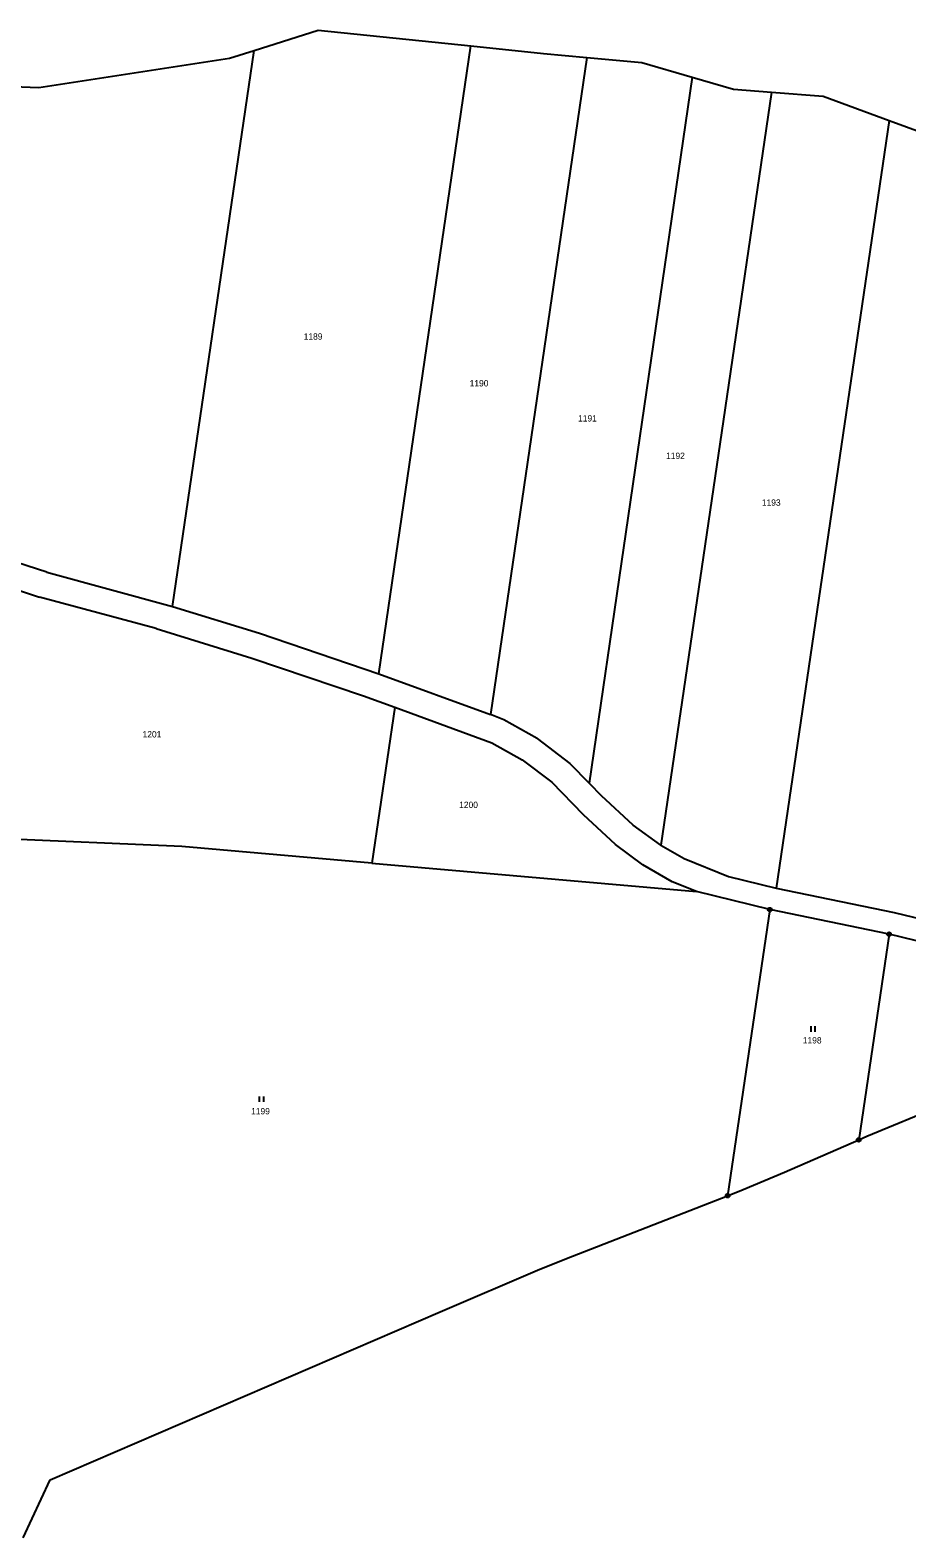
# Model space of a CAD drawing. Extents: x -796130 to -793145, y -1109506 to -1106267.
# Drawn here: x -794165.1 to -793929.1, y -1109343.1 to -1108937.3 of the extents above; entities that cross this region are included whole.
import ezdxf

# ---------------------------------------------------------------- set-up
doc = ezdxf.new("R2010")
doc.units = 0
for name, color, linetype in [('Vrstva 1', 7, 'Continuous'), ('Vrstva 14', 7, 'Continuous'), ('Vrstva 23', 7, 'Continuous'), ('Vrstva 28', 7, 'Continuous'), ('Vrstva 4', 7, 'Continuous')]:
    doc.layers.add(name, color=color, linetype=linetype)

msp = doc.modelspace()

# ---------------------------------------------------------------- linework, layer by layer
at = {"layer": 'Vrstva 1'}
for p, q in [((-794104.82, -1108942.73), (-794087.59, -1108937.28)), ((-794087.59, -1108937.28), (-794046.51, -1108941.52)), ((-794071.22, -1109110.53), (-794046.51, -1108941.52)), ((-794046.51, -1108941.52), (-794026.92, -1108943.54)), ((-794162.78, -1108952.68), (-794111.4, -1108944.81)), ((-794126.72, -1109092.42), (-794104.82, -1108942.73)), ((-794111.4, -1108944.81), (-794104.82, -1108942.73)), ((-794015.27, -1108944.62), (-794041.14, -1109121.51)), ((-794026.92, -1108943.54), (-794015.27, -1108944.62)), ((-794015.27, -1108944.62), (-794000.44, -1108945.99)), ((-794000.44, -1108945.99), (-793986.88, -1108949.93)), ((-793986.88, -1108949.93), (-794014.67, -1109139.95)), ((-793986.88, -1108949.93), (-793975.78, -1108953.15)), ((-794183.38, -1108951.9), (-794162.78, -1108952.68)), ((-793965.54, -1108953.96), (-793979.48, -1109048.73)), ((-793975.78, -1108953.15), (-793965.54, -1108953.96)), ((-793965.54, -1108953.96), (-793951.63, -1108955.05)), ((-793951.63, -1108955.05), (-793933.87, -1108961.6)), ((-793933.87, -1108961.6), (-793948.03, -1109057.9)), ((-793933.87, -1108961.6), (-793916, -1108968.2)), ((-793979.48, -1109048.73), (-793995.35, -1109156.64)), ((-793948.03, -1109057.9), (-793964.26, -1109168.26)), ((-794160.54, -1109083.19), (-794195.6, -1109071.85)), ((-794185.21, -1109082.53), (-794162.53, -1109089.9)), ((-794160.54, -1109083.19), (-794126.72, -1109092.42)), ((-794131.17, -1109098.37), (-794162.53, -1109089.9)), ((-794126.72, -1109092.42), (-794103.37, -1109099.6)), ((-794131.17, -1109098.37), (-794105.39, -1109106.3)), ((-794103.37, -1109099.6), (-794071.22, -1109110.53)), ((-794105.39, -1109106.3), (-794075.38, -1109116.47)), ((-794071.22, -1109110.53), (-794041.14, -1109121.51)), ((-794075.38, -1109116.47), (-794066.93, -1109119.55)), ((-794066.93, -1109119.55), (-794073.1, -1109161.53)), ((-794066.93, -1109119.55), (-794040.84, -1109129.07)), ((-794037.56, -1109122.88), (-794041.14, -1109121.51)), ((-794028.59, -1109127.95), (-794037.56, -1109122.88)), ((-794040.84, -1109129.07), (-794032.64, -1109133.65)), ((-794028.59, -1109127.95), (-794019.8, -1109134.66)), ((-794032.64, -1109133.65), (-794024.67, -1109139.69)), ((-794019.8, -1109134.66), (-794014.67, -1109139.95)), ((-794016.14, -1109148.5), (-794024.67, -1109139.69)), ((-794014.67, -1109139.95), (-794011.32, -1109143.41)), ((-794002.78, -1109151.3), (-794011.32, -1109143.41)), ((-794007.55, -1109156.46), (-794016.14, -1109148.5)), ((-793995.35, -1109156.64), (-794002.78, -1109151.3)), ((-794124.24, -1109157.05), (-794195.74, -1109153.92)), ((-794073.1, -1109161.53), (-794124.24, -1109157.05)), ((-794000.16, -1109161.93), (-794007.55, -1109156.46)), ((-793995.35, -1109156.64), (-793989.07, -1109160.29)), ((-794073.1, -1109161.53), (-793985.71, -1109169.17)), ((-793989.07, -1109160.29), (-793977.09, -1109165.05)), ((-793992.26, -1109166.53), (-794000.16, -1109161.93)), ((-793977.09, -1109165.05), (-793964.26, -1109168.26)), ((-793985.71, -1109169.17), (-793992.26, -1109166.53)), ((-793966.01, -1109174.01), (-793985.71, -1109169.17)), ((-793964.26, -1109168.26), (-793932.54, -1109174.79)), ((-793966.01, -1109174.01), (-793977.36, -1109251.01)), ((-793933.93, -1109180.62), (-793966.01, -1109174.01)), ((-793932.54, -1109174.79), (-793916.12, -1109178.76)), ((-793933.93, -1109180.62), (-793942.09, -1109235.98)), ((-793917.53, -1109184.59), (-793933.93, -1109180.62))]:
    msp.add_line(p, q, dxfattribs=at)
at = {"layer": 'Vrstva 23'}
for p, q in [((-793954.91, -1109206.92), (-793954.91, -1109205.42)), ((-793953.91, -1109205.42), (-793953.91, -1109206.92)), ((-794103.31, -1109225.78), (-794103.31, -1109224.28)), ((-794102.31, -1109224.28), (-794102.31, -1109225.78))]:
    msp.add_line(p, q, dxfattribs=at)
at = {"layer": 'Vrstva 28'}
for centre, radius in [((-793966.01, -1109174.01), 0.5), ((-793966.01, -1109174.01), 0.01), ((-793933.93, -1109180.62), 0.5), ((-793933.93, -1109180.62), 0.01), ((-793942.09, -1109235.98), 0.5), ((-793942.09, -1109235.98), 0.01), ((-793977.36, -1109251.01), 0.5), ((-793977.36, -1109251.01), 0.01)]:
    msp.add_circle(centre, radius, dxfattribs=at)
at = {"layer": 'Vrstva 4'}
for p, q in [((-793939.91, -1109235.03), (-793850.35, -1109197.8)), ((-793962.05, -1109244.72), (-793942.09, -1109235.98)), ((-793942.09, -1109235.98), (-793939.91, -1109235.03)), ((-793973.2, -1109249.38), (-793962.05, -1109244.72)), ((-794019.08, -1109267.3), (-793977.36, -1109251.01)), ((-793977.36, -1109251.01), (-793973.2, -1109249.38)), ((-794027.93, -1109270.75), (-794019.08, -1109267.3)), ((-794054.71, -1109282.28), (-794027.93, -1109270.75)), ((-794159.69, -1109327.5), (-794054.71, -1109282.28)), ((-794166.91, -1109343.11), (-794159.69, -1109327.5))]:
    msp.add_line(p, q, dxfattribs=at)

# ---------------------------------------------------------------- texts
at = {"layer": 'Vrstva 14'}
for s, p in [('1189', (-794091.453, -1109020.59)), ('1190', (-794046.792, -1109033.18)), ('1191', (-794017.616, -1109042.62)), ('1192', (-793993.933, -1109052.69)), ('1193', (-793968.153, -1109065.29)), ('1201', (-794134.822, -1109127.67)), ('1200', (-794049.618, -1109146.66)), ('1198', (-793957.133, -1109210.04)), ('1199', (-794105.613, -1109229.13))]:
    msp.add_text(s, height=1.7, dxfattribs=at).set_placement(p)

doc.saveas('drawing.dxf')
